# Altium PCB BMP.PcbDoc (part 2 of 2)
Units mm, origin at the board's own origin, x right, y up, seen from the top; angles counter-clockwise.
Board outline 171.87 x 76.56 mm, 2 copper layers (Top Layer, Bottom Layer); 88 components, 25 nets, 514 pads, 181 vias.
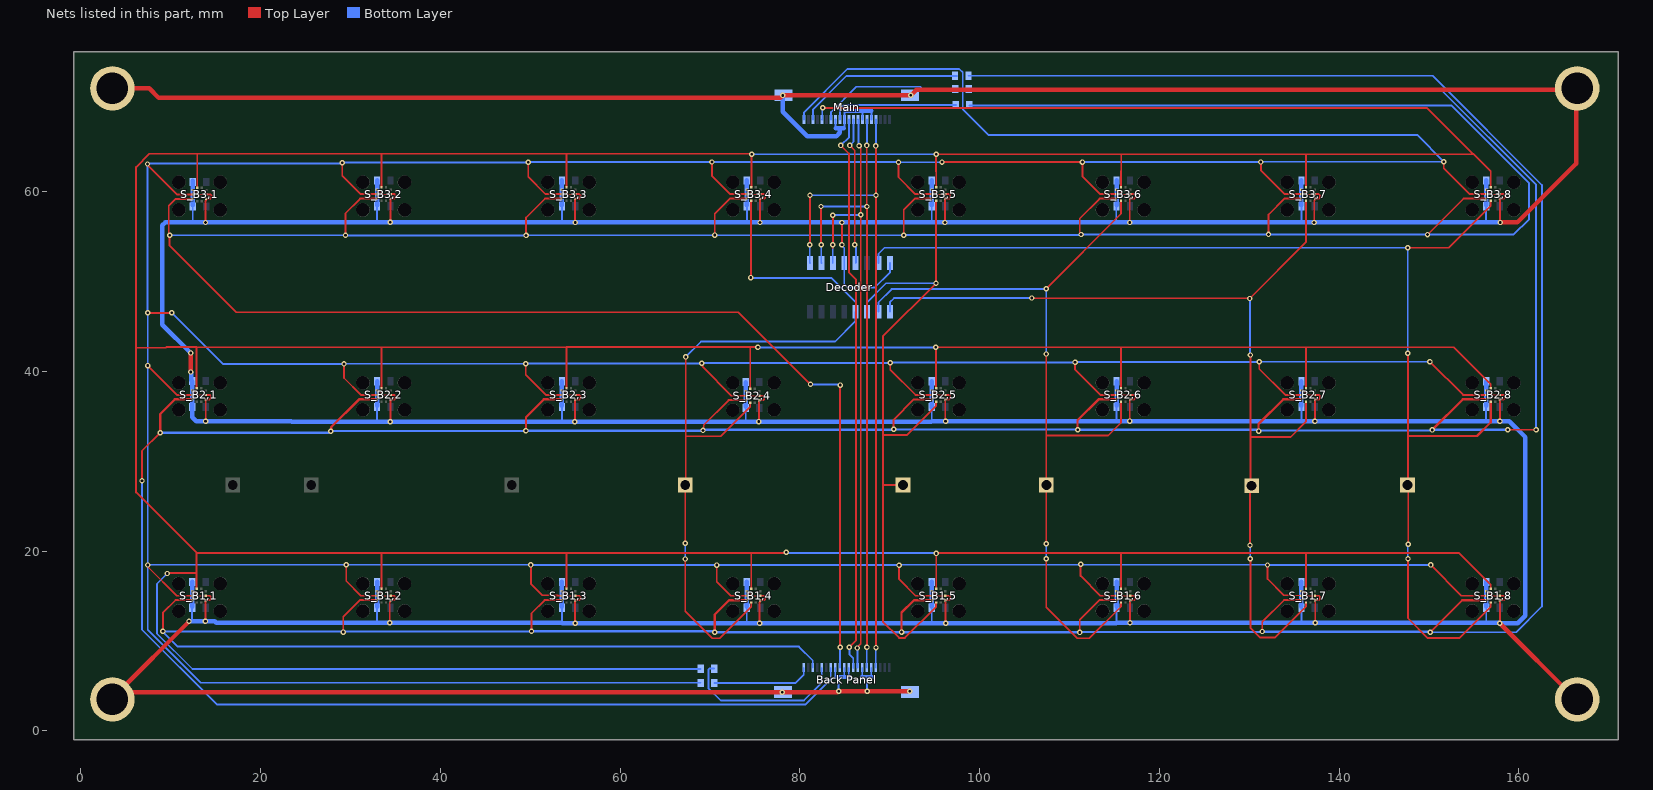
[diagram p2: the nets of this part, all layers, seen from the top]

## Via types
v1: diameter 0.6, hole 0.3, Top Layer to Bottom Layer, tented both sides, 181 vias

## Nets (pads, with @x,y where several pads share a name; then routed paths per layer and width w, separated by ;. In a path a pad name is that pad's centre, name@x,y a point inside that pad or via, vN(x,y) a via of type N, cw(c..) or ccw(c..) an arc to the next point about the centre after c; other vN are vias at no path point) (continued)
CS-4: CS-4.1 Decoder.12 S_B1,4.6 S_B2,4.6 S_B3,4.6 | length 91.5
  Top Layer w0.2: v1(67.246,19.12) 67.246,13.326 70.265,10.307 71.079,10.307 74.591,13.818 74.591,14.283 ; v1(67.246,20.886) CS-4.1@67.246,27.356 67.293,27.402 67.293,32.78 ; v1(67.293,41.613) 67.293,32.78 ; 74.466,36.536 74.466,36.046 71.201,32.78 67.293,32.78 ; v1(74.548,50.443) 74.569,50.464 74.569,58.944 74.589,58.963
  Top Layer w0.254: 74.589,58.963 74.591,58.965
  Bottom Layer w0.2: v1(67.246,19.12) v1(67.246,20.886) ; v1(67.293,41.613) 69.009,43.33 83.935,43.33 86.182,45.578 86.182,46.615 Decoder.12@86.208,46.64 86.208,47.703 83.509,50.402 74.862,50.402
CS-5: CS-5.1 Decoder.11 S_B1,5.6 S_B2,5.6 S_B3,5.6 | length 77.4
  Top Layer w0.2: CS-5.1@91.491,27.356 89.239,27.356 ; 95.164,14.283 95.164,13.818 91.687,10.341 91.046,10.341 89.239,12.149 89.239,27.356 ; 95.164,36.624 95.164,36.187 91.884,32.907 90.161,32.907 89.239,32.907 ; 95.164,58.965 95.156,58.957 95.156,49.817 89.239,43.9 89.239,32.907 ; 89.239,27.356 89.239,32.907
  Bottom Layer w0.2: Decoder.11@87.478,46.64 87.478,47.703 89.584,49.809 v1(95.148,49.809)
CS-6: CS-6.1 Decoder.10 S_B1,6.6 S_B2,6.6 S_B3,6.6 | length 91.9
  Top Layer w0.2: v1(107.399,49.208) 115.735,57.544 115.735,58.927 115.737,58.929 115.737,58.965 ; v1(107.416,19.142) 107.416,13.748 110.862,10.301 112.22,10.301 115.737,13.818 115.737,14.283 ; v1(107.425,20.836) CS-6.1@107.425,27.356 107.425,32.857 ; v1(107.425,41.938) 107.425,32.857 ; 115.737,36.624 115.737,34.304 114.289,32.857 110.634,32.857 107.425,32.857
  Bottom Layer w0.2: Decoder.10@88.748,46.64 88.748,47.703 90.2,49.155 107.347,49.155 v1(107.399,49.208) 107.412,49.195 107.412,41.95 v1(107.425,41.938) ; v1(107.416,19.142) 107.42,19.147 107.42,20.832 v1(107.425,20.836)
CS-7: CS-7.1 Decoder.9 S_B1,7.6 S_B2,7.6 S_B3,7.6 | length 109.2
  Top Layer w0.2: v1(105.799,48.166) 105.824,48.141 130.031,48.141 v1(130.056,48.116) 136.31,54.369 136.31,58.965 ; v1(130.084,20.666) 130.084,27.087 CS-7.1@130.277,27.28 130.135,27.421 130.135,32.704 ; v1(130.132,19.146) 130.132,11.453 131.182,10.403 132.885,10.403 136.31,13.827 136.31,14.283 ; v1(130.135,41.826) 130.135,32.704 ; 136.31,36.624 136.31,34.405 134.609,32.704 130.135,32.704
  Bottom Layer w0.2: Decoder.9@90.018,46.64 90.018,47.703 90.481,48.166 v1(105.799,48.166) ; v1(130.056,48.116) 130.096,48.076 130.096,41.865 v1(130.135,41.826) ; v1(130.084,20.666) 130.108,20.642 130.108,19.17 v1(130.132,19.146)
CS-8: CS-8.1 Decoder.7 S_B1,8.6 S_B2,8.6 S_B3,8.6 | length 137.4
  Top Layer w0.2: CS-8.1@147.627,27.356 147.701,27.281 v1(147.701,20.777) ; v1(147.626,42.016) 147.681,41.962 147.681,32.808 ; v1(147.658,53.754) 152.183,53.754 156.883,58.454 156.883,58.965 ; v1(147.669,19.146) 147.669,12.534 149.877,10.327 153.391,10.327 156.883,13.818 156.883,14.283
  Top Layer w0.254: CS-8.1@147.627,27.356 147.681,27.41 147.681,32.808 155.337,32.808 156.883,34.353 156.883,36.624
  Bottom Layer w0.2: Decoder.7@88.748,52.064 88.748,53.085 89.417,53.754 v1(147.658,53.754) ; v1@147.642,42.032 v1@147.642,53.739 ; v1@147.648,20.536 147.648,19.167 v1(147.669,19.146)
  Bottom Layer w0.254: v1(147.626,42.016) v1@147.642,42.032 ; v1@147.648,20.536 147.648,20.724 v1(147.701,20.777)
DEC_A0: "Back Panel.4" Decoder.1 Main.17 | length 75.9
  Top Layer w0.2: v1(81.102,54.104) 81.115,54.117 81.115,59.576 v1(81.128,59.588) ; v1@88.461,65.067 88.461,59.717 v1@88.514,59.665 ; v1@88.507,9.296 88.468,9.335 88.468,59.575 v1@88.507,59.614
  Bottom Layer w0.2: v1(81.102,54.104) 81.102,52.09 Decoder.1@81.128,52.064 ; v1(81.128,59.588) 81.14,59.601 88.456,59.601 v1(88.468,59.614) ; 88.44,7.031 88.454,7.044 88.454,9.256 v1(88.467,9.269) ; v1(88.454,65.093) 88.46,65.099 88.46,68.015 Main.17@88.466,68.021
DEC_A1: "Back Panel.6" Decoder.2 Main.15 | length 72.5
  Top Layer w0.2: v1(82.353,58.353) 82.364,58.343 82.364,54.106 v1@82.374,54.095 ; v1(87.446,65.148) 87.452,65.142 87.452,58.355 87.46,58.347 v1@87.46,9.182
  Bottom Layer w0.2: v1(82.353,58.353) v1(87.458,58.353) ; v1@82.374,54.095 82.374,52.088 Decoder.2@82.398,52.064 ; 87.44,7.031 87.451,7.041 87.451,9.286 v1(87.461,9.296) ; v1@87.446,65.151 87.456,65.161 87.456,68.011 Main.15@87.466,68.021
  other v1: 82.374,54.104
DEC_A2: "Back Panel.8" Decoder.3 Main.13 | length 69.7
  Top Layer w0.2: 83.668,53.746 83.668,54.102 83.67,54.104 83.67,57.375 v1(83.673,57.378) ; v1(86.385,9.22) 86.385,9.32 86.781,9.715 v1(86.781,57.438) ; v1(86.589,65.126) 86.589,65.017 86.781,64.825 v1@86.781,57.461
  Bottom Layer w0.2: Decoder.3@83.668,52.064 83.668,53.746 ; v1(83.673,57.378) 83.703,57.408 86.751,57.408 v1(86.781,57.438) ; v1(86.385,9.22) 86.413,9.193 86.413,7.059 86.44,7.031 ; Main.13@86.466,68.021 86.516,67.971 86.516,65.198 v1(86.589,65.126)
  other v1: 83.668,54.104
DEC_E3_1: Decoder.5 Main.12 | length 16.4
  Top Layer w0.2: v1(85.544,65.148) 86.106,64.586 v1(86.106,54.104)
  Bottom Layer w0.2: v1(85.544,65.148) 85.544,65.152 85.966,65.574 Main.12@85.966,68.021 ; v1(86.106,54.104) 86.106,53.996 86.233,53.869 86.233,52.09 Decoder.5@86.208,52.064
DEC_E3_2: "Back Panel.9" Main.11 | length 62.6
  Top Layer w0.2: v1@84.557,65.075 84.63,65.075 85.452,64.253 85.452,51.045 86.239,50.258 86.239,10.03 v1(85.506,9.296)
  Bottom Layer w0.2: v1(84.557,65.148) 85.471,66.063 85.471,68.016 Main.11@85.466,68.021 ; v1(85.506,9.296) 85.506,8.527 85.94,8.092 85.94,7.031 85.94,6.985
GND: "Back Panel.5" "Back Panel.7" "Back Panel.10" "Back Panel.11" "Back Panel.13" "Back Panel.MP1" "Back Panel.MP2" C1_B1,1.1 C1_B1,2.1 C1_B1,3.1 C1_B1,4.1 C1_B1,5.1 C1_B1,6.1 C1_B1,7.1 C1_B1,8.1 C1_B2,1.1 C1_B2,2.1 C1_B2,3.1 C1_B2,4.1 C1_B2,5.1 C1_B2,6.1 C1_B2,7.1 C1_B2,8.1 C1_B3,1.1 C1_B3,2.1 C1_B3,3.1 C1_B3,4.1 C1_B3,5.1 C1_B3,6.1 C1_B3,7.1 C1_B3,8.1 C2_B1,1.1 C2_B1,2.1 C2_B1,3.1 C2_B1,4.1 C2_B1,5.1 C2_B1,6.1 C2_B1,7.1 C2_B1,8.1 C2_B2,1.1 C2_B2,2.1 C2_B2,3.1 C2_B2,4.1 C2_B2,5.1 C2_B2,6.1 C2_B2,7.1 C2_B2,8.1 C2_B3,1.1 C2_B3,2.1 C2_B3,3.1 C2_B3,4.1 C2_B3,5.1 C2_B3,6.1 C2_B3,7.1 C2_B3,8.1 Decoder.4 Decoder.8 Main.8 Main.10 Main.14 Main.16 Main.MP1 Main.MP2 pad.1 pad.2@166.5,3.5 pad.3@166.5,71.5 pad.4@3.5,71.5 S_B1,1.3 S_B1,1.8 S_B1,1.9 S_B1,2.3 S_B1,2.8 S_B1,2.9 S_B1,3.3 S_B1,3.8 S_B1,3.9 S_B1,4.3 S_B1,4.8 S_B1,4.9 S_B1,5.3 S_B1,5.8 S_B1,5.9 S_B1,6.3 S_B1,6.8 S_B1,6.9 S_B1,7.3 S_B1,7.8 S_B1,7.9 S_B1,8.3 S_B1,8.8 S_B1,8.9 S_B2,1.3 S_B2,1.8 S_B2,1.9 S_B2,2.3 S_B2,2.8 S_B2,2.9 S_B2,3.3 S_B2,3.8 S_B2,3.9 S_B2,4.3 S_B2,4.8 S_B2,4.9 S_B2,5.3 S_B2,5.8 S_B2,5.9 S_B2,6.3 S_B2,6.8 S_B2,6.9 S_B2,7.3 S_B2,7.8 S_B2,7.9 S_B2,8.3 S_B2,8.8 S_B2,8.9 S_B3,1.3 S_B3,1.8 S_B3,1.9 S_B3,2.3 S_B3,2.8 S_B3,2.9 S_B3,3.3 S_B3,3.8 S_B3,3.9 S_B3,4.3 S_B3,4.8 S_B3,4.9 S_B3,5.3 S_B3,5.8 S_B3,5.9 S_B3,6.3 S_B3,6.8 S_B3,6.9 S_B3,7.3 S_B3,7.8 S_B3,7.9 S_B3,8.3 S_B3,8.8 S_B3,8.9 | length 1067.2
  Top Layer w0.127: 12.359,15.546 12.421,15.485 12.561,15.485 12.999,15.046 13.883,15.046 ; 12.359,37.887 12.421,37.826 12.561,37.826 12.999,37.387 13.883,37.387 ; 12.436,60.2 12.497,60.138 12.637,60.138 13.076,59.7 13.96,59.7 ; 32.932,15.546 32.994,15.485 33.134,15.485 33.572,15.046 34.456,15.046 ; 32.932,37.887 32.994,37.826 33.134,37.826 33.572,37.387 34.456,37.387 ; 32.932,60.228 32.994,60.166 33.134,60.166 33.572,59.728 34.456,59.728 ; 53.505,15.546 53.567,15.485 53.707,15.485 54.145,15.046 55.029,15.046 ; 53.505,37.887 53.567,37.826 53.707,37.826 54.145,37.387 55.029,37.387 ; 53.505,60.228 53.567,60.166 53.707,60.166 54.145,59.728 55.029,59.728 ; 73.954,37.799 74.016,37.737 74.156,37.737 74.594,37.299 75.478,37.299 ; 74.078,15.546 74.14,15.485 74.28,15.485 74.718,15.046 75.602,15.046 ; 74.078,60.228 74.14,60.166 74.28,60.166 74.718,59.728 75.602,59.728 ; 94.651,15.546 94.713,15.485 94.853,15.485 95.291,15.046 96.175,15.046 ; 94.651,37.887 94.713,37.826 94.853,37.826 95.291,37.387 96.175,37.387 ; 94.651,60.228 94.713,60.166 94.853,60.166 95.291,59.728 96.175,59.728 ; 115.224,15.546 115.286,15.485 115.426,15.485 115.864,15.046 116.748,15.046 ; 115.224,37.887 115.286,37.826 115.426,37.826 115.864,37.387 116.748,37.387 ; 115.224,60.228 115.286,60.166 115.426,60.166 115.864,59.728 116.748,59.728 ; 135.797,15.546 135.859,15.485 135.999,15.485 136.437,15.046 137.321,15.046 ; 135.797,37.887 135.859,37.826 135.999,37.826 136.437,37.387 137.321,37.387 ; 135.797,60.228 135.859,60.166 135.999,60.166 136.437,59.728 137.321,59.728 ; 156.37,15.546 156.432,15.485 156.572,15.485 157.01,15.046 157.894,15.046 ; 156.37,37.887 156.432,37.826 156.572,37.826 157.01,37.387 157.894,37.387 ; 156.37,60.228 156.432,60.166 156.572,60.166 157.01,59.728 157.894,59.728
  Top Layer w0.2: v1(13.851,12.2) 13.867,12.216 13.867,14.53 13.883,14.546 14.321,14.546 14.438,14.664 14.438,14.919 14.311,15.046 13.883,15.046 ; v1(13.858,56.574) 13.873,56.588 13.873,58.975 13.922,59.024 13.922,59.175 13.947,59.2 13.96,59.2 14.397,59.2 14.514,59.317 14.514,59.573 14.387,59.7 13.96,59.7 ; v1@13.883,34.628 13.883,36.887 14.321,36.887 14.438,37.004 14.438,37.26 14.311,37.387 13.883,37.387 ; v1@34.369,12.014 34.369,14.321 34.419,14.371 34.419,14.521 34.444,14.546 34.456,14.546 34.894,14.546 35.011,14.664 35.011,14.919 34.884,15.046 34.456,15.046 ; v1(34.424,34.399) 34.44,34.415 34.44,36.871 34.456,36.887 34.894,36.887 35.011,37.004 35.011,37.26 34.884,37.387 34.456,37.387 ; v1(34.427,56.601) 34.442,56.616 34.442,59.213 34.456,59.228 34.894,59.228 35.011,59.345 35.011,59.601 34.884,59.728 34.456,59.728 ; v1(54.992,11.963) 54.992,14.521 55.017,14.546 55.029,14.546 55.467,14.546 55.584,14.664 55.584,14.919 55.457,15.046 55.029,15.046 ; v1@54.992,34.412 54.992,36.862 55.017,36.887 55.029,36.887 55.467,36.887 55.584,37.004 55.584,37.26 55.457,37.387 55.029,37.387 ; v1(54.992,56.574) 54.992,59.203 55.017,59.228 55.029,59.228 55.467,59.228 55.584,59.345 55.584,59.601 55.457,59.728 55.029,59.728 ; v1@75.441,34.628 75.441,36.774 75.466,36.799 75.478,36.799 75.916,36.799 76.033,36.916 76.033,37.172 75.906,37.299 75.478,37.299 ; v1@75.515,11.996 75.515,14.289 75.565,14.339 75.565,14.521 75.59,14.546 75.602,14.546 76.04,14.546 76.157,14.664 76.157,14.919 76.03,15.046 75.602,15.046 ; v1(75.565,56.574) 75.565,59.203 75.59,59.228 75.602,59.228 76.04,59.228 76.157,59.345 76.157,59.601 76.03,59.728 75.602,59.728 ; v1(84.677,54.104) v1(84.677,56.568) ; v1(96.138,56.574) 96.138,59.203 96.163,59.228 96.175,59.228 96.613,59.228 96.73,59.345 96.73,59.601 96.603,59.728 96.175,59.728 ; 96.175,15.046 96.603,15.046 96.73,14.919 96.73,14.664 96.613,14.546 96.175,14.546 96.199,14.523 v1@96.199,11.963 ; v1@96.175,34.627 96.175,36.887 96.613,36.887 96.73,37.004 96.73,37.26 96.603,37.387 96.175,37.387 ; v1@116.711,34.499 116.711,36.862 116.736,36.887 116.748,36.887 117.186,36.887 117.303,37.004 117.303,37.26 117.176,37.387 116.748,37.387 ; v1(116.711,56.574) 116.711,59.203 116.736,59.228 116.748,59.228 117.186,59.228 117.303,59.345 117.303,59.601 117.176,59.728 116.748,59.728 ; v1(116.738,12.014) 116.738,14.536 116.748,14.546 117.186,14.546 117.303,14.664 117.303,14.919 117.176,15.046 116.748,15.046 ; v1@137.234,56.842 137.234,59.003 137.284,59.052 137.284,59.203 137.309,59.228 137.321,59.228 137.759,59.228 137.876,59.345 137.876,59.601 137.749,59.728 137.321,59.728 ; 137.321,15.046 137.749,15.046 137.876,14.919 137.876,14.664 137.759,14.546 137.321,14.546 137.342,14.526 137.342,12.035 v1(137.363,12.014) ; 137.321,36.887 137.317,36.883 137.317,34.632 v1@137.359,34.59 ; 137.321,37.387 137.749,37.387 137.876,37.26 137.876,37.004 137.759,36.887 137.334,36.887 ; v1(157.886,11.989) 157.894,11.997 157.894,14.407 ; 157.894,14.546 158.332,14.546 158.449,14.664 158.449,14.919 158.322,15.046 157.894,15.046 ; 157.894,37.387 158.322,37.387 158.449,37.26 158.449,37.004 158.332,36.887 157.894,36.887 157.898,36.883 157.898,34.454 v1(157.902,34.45) ; 157.894,59.728 158.322,59.728 158.449,59.601 158.449,59.345 158.332,59.228 157.895,59.228 157.92,59.203 v1@157.92,56.599
  Top Layer w0.5: pad.1@3.5,3.5 3.5,3.651 pad.1@4.15,4.3 ; pad.4@3.5,71.5 7.596,71.5 8.661,70.434 77.799,70.434 78.078,70.714 v1(78.105,70.714) ; v1(12.022,12.2) 12.022,12.173 pad.1@4.15,4.3 ; v1(12.218,39.937) v1(12.218,42.053) ; v1@78.151,70.726 v1@92.316,70.726 ; v1(92.236,4.418) 92.165,4.418 92.141,4.394 84.312,4.394 v1(84.309,4.397) 84.282,4.397 84.198,4.313 v1(78.034,4.313) 78.015,4.294 4.156,4.294 pad.1@4.15,4.3 ; v1(92.329,70.739) 92.356,70.739 92.94,71.323 pad.3@166.37,71.323 ; v1(157.886,11.989) 166.375,3.5 pad.2@166.5,3.5 ; v1@157.92,56.599 v1(157.945,56.574) 159.837,56.574 166.395,63.132 166.395,71.395 pad.3@166.5,71.5
  Bottom Layer w0.2: 12.372,12.2 12.372,13.699 ; 12.448,56.574 12.448,58.352 ; 32.945,12.251 32.945,13.699 ; 32.945,34.527 32.945,36.039 ; 32.945,56.65 32.945,58.38 ; 53.518,11.989 53.518,12.014 53.518,13.699 ; 53.518,34.508 53.518,36.039 ; 53.518,56.587 53.518,58.38 ; 73.966,35.951 73.981,35.936 73.981,35.115 73.981,34.628 ; 74.091,12.141 74.091,13.699 ; 74.091,58.38 74.125,58.345 74.125,56.574 ; v1(78.105,70.714) 78.113,70.721 Main.MP1@78.166,70.721 ; 83.94,7.031 83.94,6.084 84.03,5.994 ; 83.966,67.071 Main.8@83.966,68.021 ; v1(84.309,4.397) 84.309,5.994 ; v1(84.677,54.104) 84.677,53.996 84.938,53.736 Decoder.4@84.938,52.064 84.938,50.562 84.931,50.556 84.931,49.716 85.315,49.333 88.349,49.333 90.018,51.002 Decoder.8@90.018,52.064 ; 84.836,5.994 84.94,6.099 84.94,7.031 ; 84.881,67.071 84.966,67.156 Main.10@84.966,68.021 84.966,68.905 85.056,68.995 ; 85.44,7.031 85.44,6.136 85.582,5.994 ; 86.893,5.99 86.94,6.037 86.94,7.031 ; Main.14@86.966,68.021 86.966,69.012 ; 87.475,5.99 87.475,4.427 v1(87.49,4.412) ; 87.94,7.031 87.94,6.106 88.057,5.99 ; Main.16@87.966,68.021 87.966,69.012 ; 94.664,12.014 94.664,13.699 ; 94.664,34.45 94.664,35.939 ; 94.664,56.574 94.664,58.38 ; 115.197,56.574 115.197,58.34 115.237,58.38 ; 115.237,12.014 115.237,13.699 ; 115.237,34.508 115.237,36.039 ; 135.81,12.094 135.81,13.699 ; 135.81,34.468 135.81,36.039 ; 135.81,56.808 135.81,58.38 ; 156.345,34.45 156.345,36.002 156.383,36.039 156.383,36.172 ; 156.345,56.574 156.345,58.342 156.383,58.38 ; 156.383,12.008 156.383,13.699
  Bottom Layer w0.5: v1(12.022,12.2) 12.372,12.2 v1(13.851,12.2) 13.87,12.181 14.873,12.181 15.04,12.014 v1(34.366,12.014) 53.518,12.014 53.568,11.963 v1(54.992,11.963) v1(75.514,11.963) v1(96.241,11.963) ; v1(12.218,39.937) 12.218,39.91 12.278,39.85 12.278,39.021 12.378,38.921 ; v1(12.218,42.053) 9.06,45.21 9.06,56.247 9.387,56.574 12.448,56.574 v1(13.858,56.574) 13.872,56.587 34.413,56.587 v1(34.427,56.601) 34.44,56.587 53.518,56.587 54.978,56.587 v1(54.992,56.574) 74.125,56.574 v1(75.565,56.574) 75.568,56.571 84.674,56.571 v1(84.677,56.568) ; 12.371,13.831 12.371,16.566 ; 12.372,36.039 12.372,34.886 12.815,34.442 v1(13.868,34.442) 23.398,34.442 23.442,34.399 v1(34.424,34.399) 54.947,34.399 v1(54.961,34.412) ; 12.371,36.172 12.375,36.175 12.375,38.904 ; 12.438,58.494 12.438,61.21 ; 32.944,13.831 32.944,16.566 ; 32.944,36.172 32.944,38.907 ; 32.944,58.513 32.944,61.247 ; 53.517,13.831 53.517,16.566 ; 53.517,36.172 53.517,38.907 ; 53.517,58.513 53.517,61.247 ; 73.966,36.084 73.966,38.819 ; 74.09,13.831 74.09,16.566 ; 74.09,58.513 74.09,61.247 ; v1(78.105,70.714) 78.105,68.88 80.805,66.179 84.072,66.179 84.441,66.548 84.441,67.071 ; 83.966,67.071 84.441,67.071 ; 84.03,5.994 84.309,5.994 84.836,5.994 85.582,5.994 ; v1@84.724,56.574 94.664,56.574 v1(96.138,56.574) 115.197,56.574 v1(116.711,56.574) v1(137.22,56.574) 156.345,56.574 v1(157.945,56.574) ; 84.881,67.071 84.441,67.071 ; 85.056,68.995 85.073,69.012 86.966,69.012 87.966,69.012 ; 86.893,5.99 87.475,5.99 88.057,5.99 ; 94.663,13.831 94.663,16.566 ; 94.663,36.172 94.663,38.907 ; 94.663,58.513 94.663,61.247 ; v1@96.287,11.963 115.186,11.963 115.237,12.014 v1(116.738,12.014) v1(137.363,12.014) 137.369,12.008 156.383,12.008 157.84,12.008 v1@157.854,12.021 ; 115.236,13.831 115.236,16.566 ; 115.236,36.172 115.236,38.907 ; 115.236,58.513 115.236,61.247 ; 135.809,13.831 135.809,16.566 ; 135.809,36.172 135.809,38.907 ; 135.809,58.513 135.809,61.247 ; v1(137.312,34.45) 156.345,34.45 v1(157.902,34.45) 158.955,34.45 160.71,32.696 160.71,12.811 159.888,11.989 v1(157.886,11.989) ; 156.382,13.831 156.382,16.566 ; 156.382,36.172 156.382,38.907 ; 156.382,58.513 156.382,61.247
  Bottom Layer w0.508: v1(54.961,34.412) 54.966,34.417 v1(75.413,34.417) 94.63,34.417 94.664,34.45 v1(96.212,34.45) 115.745,34.45 115.751,34.457 116.687,34.457 v1(116.705,34.475) ; 94.664,35.939 94.664,36.039 ; v1@116.736,34.457 117.765,34.457 117.772,34.45 v1(137.312,34.45)
MISO-1: "Back Panel.18" R3.1 S_B1,1.5 S_B1,2.5 S_B1,3.5 S_B1,4.5 S_B1,5.5 S_B1,6.5 S_B1,7.5 S_B1,8.5 | length 396
  Top Layer w0.2: v1(9.119,11.1) 9.119,13.146 10.52,14.546 12.359,14.546 ; v1(29.182,10.995) 29.182,12.712 31.016,14.546 32.932,14.546 ; v1(50.136,11.099) 50.136,13.093 51.589,14.546 53.505,14.546 ; v1(111.133,10.955) 111.133,12.371 113.308,14.546 115.224,14.546 ; v1(131.453,11.057) 131.453,12.127 133.872,14.546 135.797,14.546
  Top Layer w0.254: v1(70.536,10.961) 70.536,12.959 72.124,14.546 74.078,14.546 ; v1(91.317,10.995) 91.317,13.167 92.697,14.546 94.651,14.546 ; v1(150.147,10.981) 153.713,14.546 156.37,14.546
  Bottom Layer w0.2: v1(9.119,11.1) 9.119,11.015 10.755,9.379 79.892,9.379 81.44,7.831 81.44,7.031 ; v1@9.122,11.048 29.13,11.048 v1(29.182,10.995) 29.234,11.047 50.084,11.047 v1(50.136,11.099) ; R3.1@98.769,72.898 150.413,72.898 162.579,60.732 162.579,13.845 159.715,10.981 v1(150.147,10.981)
  Bottom Layer w0.254: v1(50.136,11.099) 70.305,11.099 70.443,10.961 v1(70.536,10.961) 70.554,10.978 91.3,10.978 v1(91.317,10.995) 91.337,10.975 111.113,10.975 v1(111.133,10.955) 111.184,11.006 131.402,11.006 v1(131.453,11.057) 131.491,11.019 150.109,11.019 v1(150.147,10.981)
MOSI-1: Main.1 R4.1 S_B1,1.4 S_B1,2.4 S_B1,3.4 S_B1,4.4 S_B1,5.4 S_B1,6.4 S_B1,7.4 S_B1,8.4 S_B2,1.4 S_B2,2.4 S_B2,3.4 S_B2,4.4 S_B2,5.4 S_B2,6.4 S_B2,7.4 S_B2,8.4 S_B3,1.4 S_B3,2.4 S_B3,3.4 S_B3,4.4 S_B3,5.4 S_B3,6.4 S_B3,7.4 S_B3,8.4 | length 781.9
  Top Layer w0.2: v1(7.399,63.076) 7.476,63 7.476,62.876 10.653,59.7 12.436,59.7 ; v1(7.425,40.648) 7.425,40.612 10.65,37.387 12.359,37.387 ; v1(7.425,46.515) v1(10.092,46.515) ; v1(7.442,18.46) 7.519,18.384 7.519,18.178 10.65,15.046 12.359,15.046 ; v1(29.071,63.209) 29.071,61.778 31.121,59.728 32.932,59.728 ; v1(29.269,40.834) 29.269,39.265 31.147,37.387 32.932,37.387 ; v1(29.515,18.491) 29.515,16.679 31.147,15.046 32.932,15.046 ; v1(49.494,40.86) 49.494,39.613 51.72,37.387 53.505,37.387 ; v1(49.768,63.268) 49.768,61.654 51.694,59.728 53.505,59.728 ; v1(50.063,18.466) 50.063,16.383 51.341,15.105 52.618,15.07 52.624,15.07 52.984,15.07 53.106,15.057 53.505,15.046 ; v1(69.096,40.902) 69.173,40.826 69.173,40.507 72.381,37.299 73.954,37.299 ; v1(70.214,63.305) 70.214,61.781 72.267,59.728 74.078,59.728 ; v1(70.742,18.448) 70.742,16.597 72.293,15.046 74.078,15.046 ; v1(90.051,40.978) 90.051,40.202 92.866,37.387 94.651,37.387 ; v1(90.97,63.271) 90.97,61.598 92.84,59.728 94.651,59.728 ; v1(91.039,18.442) 91.039,16.873 92.866,15.046 94.651,15.046 ; v1(95.818,63.296) 95.819,63.294 111.44,63.294 v1(111.442,63.293) 111.442,61.699 113.413,59.728 115.224,59.728 ; v1(110.625,41.004) 110.625,40.201 113.439,37.387 115.224,37.387 ; v1(111.241,18.535) 111.241,17.244 113.439,15.046 115.224,15.046 ; v1(131.123,41.08) 131.123,40.267 134.003,37.387 135.797,37.387 ; v1(131.301,63.305) 131.301,62.404 133.977,59.728 135.797,59.728 ; v1(132.037,18.457) 132.037,16.908 133.835,15.11 135.797,15.046 ; v1(150.113,41.08) 153.805,37.387 156.37,37.387 ; v1(150.191,18.467) 153.611,15.046 156.37,15.046 ; v1(151.657,63.335) 151.657,62.63 154.559,59.728 156.37,59.728
  Bottom Layer w0.2: v1(7.399,63.076) 7.412,63.064 7.412,46.515 7.425,46.503 v1(7.425,40.648) 7.442,40.631 v1(7.442,18.46) ; v1@7.425,63.076 7.491,63.143 29.004,63.143 29.101,63.239 49.738,63.239 49.786,63.287 70.195,63.287 v1(70.214,63.305) 70.231,63.288 90.953,63.288 v1(90.97,63.271) 90.983,63.283 95.805,63.283 v1(95.818,63.296) ; v1(10.092,46.515) 15.773,40.834 v1(29.269,40.834) ; v1@29.337,40.818 29.366,40.847 49.482,40.847 v1(49.494,40.86) ; v1@49.554,40.842 49.593,40.881 69.075,40.881 69.134,40.94 90.013,40.94 90.064,40.991 110.612,40.991 110.663,41.042 131.085,41.042 v1(131.123,41.08) v1(150.113,41.08) ; R4.1@68.973,5.359 13.312,5.359 7.442,11.229 v1(7.442,18.46) ; Main.1@80.466,68.021 80.466,68.821 85.293,73.648 97.743,73.648 98.119,73.272 98.119,69.162 100.964,66.316 148.686,66.316 151.657,63.345 v1(151.657,63.335) 151.642,63.32 131.316,63.32 131.295,63.299 111.448,63.299 v1(111.442,63.293) ; v1@132.037,18.442 132.057,18.462 150.186,18.462 v1(150.191,18.467) ; v1(132.037,18.457) 132.003,18.492 111.284,18.492 v1(111.241,18.535) 111.195,18.488 91.085,18.488 v1(91.039,18.442) 91.036,18.445 70.745,18.445 70.733,18.457 50.072,18.457 50.051,18.479 29.527,18.479 v1(29.515,18.491) 29.499,18.476 7.458,18.476 v1(7.442,18.46)
MOSI-2: "Back Panel.14" R2.1 S_B2,1.5 S_B2,2.5 S_B2,3.5 S_B2,4.5 S_B2,5.5 S_B2,6.5 S_B2,7.5 S_B2,8.5 | length 406
  Top Layer w0.2: v1(6.788,27.846) 6.788,31.153 v1(8.818,33.182) ; v1@69.26,33.471 69.298,33.51 69.298,34.034 72.067,36.803 72.991,36.803 72.995,36.799 73.954,36.799 ; v1(90.432,33.561) 90.432,34.629 92.69,36.887 94.651,36.887 ; v1(158.758,33.511) v1(161.925,33.511)
  Top Layer w0.254: v1(8.818,33.182) 8.818,35.268 10.436,36.887 12.359,36.887 ; v1(27.796,33.333) 27.862,33.399 27.862,33.816 30.933,36.887 32.932,36.887 ; v1(49.513,33.384) 49.513,34.894 51.506,36.887 53.505,36.887 ; v1(69.223,33.434) v1@69.26,33.471 ; v1(110.904,33.511) 110.904,34.566 113.225,36.887 115.214,36.887 ; v1(131.047,33.358) 131.047,34.145 133.789,36.887 135.797,36.887 ; v1(150.354,33.489) 153.753,36.887 156.37,36.887
  Bottom Layer w0.2: v1(6.788,27.846) 6.788,11.261 15.108,2.941 80.632,2.941 83.44,5.75 83.44,7.031 ; R2.1@98.794,71.425 151.264,71.425 161.925,60.764 v1(161.925,33.511)
  Bottom Layer w0.254: v1(8.818,33.182) 27.551,33.182 27.702,33.333 v1(27.796,33.333) 27.821,33.358 49.487,33.358 49.538,33.409 69.198,33.409 69.287,33.498 90.369,33.498 v1(90.432,33.561) 90.457,33.536 110.879,33.536 v1(110.904,33.511) 130.801,33.511 130.953,33.358 v1(131.047,33.358) 131.112,33.423 150.289,33.423 v1(150.354,33.489) ; v1@150.365,33.5 v1@158.741,33.5
MOSI-3: "Back Panel.12" R1.1 S_B3,1.5 S_B3,2.5 S_B3,3.5 S_B3,4.5 S_B3,5.5 S_B3,6.5 S_B3,7.5 S_B3,8.5 | length 389.7
  Top Layer w0.2: 12.436,59.2 10.537,59.2 9.77,58.433 9.77,55.356 9.864,55.262 9.864,54.006 17.289,46.582 73.119,46.582 v1@81.144,38.557 ; v1(29.439,55.143) 29.439,57.605 31.062,59.228 32.932,59.228 ; v1(49.532,55.132) 49.532,57.125 51.635,59.228 53.505,59.228 ; v1(70.532,55.17) 70.532,57.552 72.208,59.228 74.078,59.228 ; v1(84.48,38.481) 84.48,9.322 v1(84.506,9.296) ; v1(91.55,55.145) 91.55,57.997 92.781,59.228 94.651,59.228 ; v1@111.14,55.45 111.14,57.014 113.354,59.228 115.224,59.228 ; v1(132.153,55.243) 132.153,57.463 133.918,59.228 135.797,59.228 ; v1(149.843,55.228) 153.843,59.228 156.37,59.228
  Top Layer w0.254: v1@81.144,38.557 v1(81.178,38.557)
  Bottom Layer w0.2: v1(9.864,55.154) 9.869,55.149 29.433,55.149 29.444,55.138 49.526,55.138 v1(49.532,55.132) 49.551,55.151 70.513,55.151 v1(70.532,55.17) ; v1@70.562,55.2 70.605,55.157 91.538,55.157 v1(91.55,55.145) ; v1(81.178,38.557) 84.404,38.557 v1(84.48,38.481) ; 84.44,7.031 84.473,7.064 84.473,9.264 v1(84.506,9.296) ; v1@91.596,55.185 91.599,55.188 111.248,55.188 v1(111.291,55.231) ; R1.1@98.858,69.596 152.47,69.596 161.147,60.92 161.147,56.917 159.387,55.228 v1(149.843,55.228) 149.835,55.236 132.16,55.236 v1@132.159,55.237 ; v1@111.298,55.237 132.146,55.237 v1(132.153,55.243)
"NetBack Panel_16": "Back Panel.16" R5.2 | length 18.4
  Bottom Layer w0.2: R5.2@70.473,6.909 70.448,6.934 69.94,6.934 69.823,6.817 69.823,4.76 71.202,3.381 80.449,3.381 82.44,5.372 82.44,7.031
"NetBack Panel_20": "Back Panel.20" R4.2 | length 11.1
  Bottom Layer w0.2: R4.2@70.473,5.334 79.543,5.334 80.44,6.231 80.44,7.031
NetMain_3: Main.3 R3.2 | length 18.7
  Bottom Layer w0.2: Main.3@81.466,68.021 81.466,69.182 85.157,72.873 R3.2@97.49,72.873
NetMain_7: Main.7 R2.2 | length 15.9
  Bottom Layer w0.2: Main.7@83.466,68.021 83.466,68.862 86.276,71.671 93.391,71.671 93.637,71.425 R2.2@97.294,71.425
NetMain_9: Main.9 R1.2 | length 14.3
  Bottom Layer w0.2: Main.9@84.466,68.021 84.466,69.24 84.873,69.647 R1.2@97.358,69.647
SCK-1: Main.5 R5.1 S_B1,1.2 S_B1,2.2 S_B1,3.2 S_B1,4.2 S_B1,5.2 S_B1,6.2 S_B1,7.2 S_B1,8.2 S_B2,1.2 S_B2,2.2 S_B2,3.2 S_B2,4.2 S_B2,5.2 S_B2,6.2 S_B2,7.2 S_B2,8.2 S_B3,1.2 S_B3,2.2 S_B3,3.2 S_B3,4.2 S_B3,5.2 S_B3,6.2 S_B3,7.2 S_B3,8.2 | length 732.7
  Top Layer w0.2: v1(9.609,17.509) 9.651,17.551 12.872,17.551 ; 12.872,15.809 12.872,17.551 ; 12.872,38.15 12.872,42.699 ; 12.948,60.463 12.948,62.36 12.948,64.219 ; 33.445,15.809 33.445,19.683 ; 33.445,38.15 33.445,42.699 ; 33.445,60.491 33.434,60.501 33.434,64.219 ; 54.018,15.809 54.018,19.8 ; 54.018,38.15 54.018,40.435 54.034,40.452 54.034,42.699 ; 54.018,60.491 54.018,64.219 ; 74.466,38.062 74.466,40.402 74.466,42.705 ; 74.591,15.809 74.591,19.8 ; 74.591,60.491 74.616,60.516 74.616,64.127 v1(74.649,64.161) 74.591,64.219 54.018,64.219 ; v1(75.332,42.676) 75.303,42.705 74.466,42.705 ; v1(78.474,19.868) 78.405,19.8 74.591,19.8 ; v1(82.532,69.323) 149.756,69.323 154.875,64.204 154.954,64.204 156.883,62.276 156.883,60.491 ; v1@95.149,42.677 95.149,38.165 95.164,38.15 ; 95.164,15.809 95.175,15.821 95.175,19.734 95.241,19.8 115.737,19.8 ; 95.164,60.491 95.164,60.525 95.167,60.528 95.167,62.252 95.164,62.256 95.164,64.158 v1(95.17,64.164) 115.756,64.164 ; v1@95.171,42.699 115.737,42.699 ; 115.737,15.809 115.737,19.8 ; 115.737,38.15 115.737,42.699 ; 115.737,60.491 115.737,62.337 115.756,62.356 115.756,64.164 ; 136.31,15.809 136.31,19.683 136.427,19.8 ; 136.31,38.15 136.31,42.699 ; 136.31,60.491 136.31,62.341 136.319,62.351 136.319,64.164 ; 154.915,64.164 136.319,64.164 ; 156.883,15.809 156.883,16.247 153.33,19.8 136.427,19.8 ; 156.883,38.15 156.883,38.588 152.771,42.699 136.31,42.699 ; 6.134,42.64 6.134,62.736 7.618,64.219 12.948,64.219 ; 6.134,42.64 6.134,26.537 12.872,19.8 ; 6.134,42.64 9.465,42.64 9.532,42.707 12.864,42.707 12.872,42.699 ; 12.872,17.551 12.872,19.8 ; 12.872,19.8 54.018,19.8 ; 12.872,42.699 33.445,42.699 ; 12.948,64.219 33.434,64.219 ; 33.434,64.219 54.018,64.219 ; 33.445,42.699 54.034,42.699 ; 54.018,19.8 74.591,19.8 ; 54.034,42.699 54.04,42.705 74.466,42.705 ; 115.737,19.8 136.427,19.8 ; 115.737,42.699 136.31,42.699 ; 115.756,64.164 136.319,64.164
  Bottom Layer w0.2: v1(9.609,17.509) 8.465,16.364 8.465,10.829 12.41,6.883 R5.1@68.973,6.883 ; v1(74.649,64.161) 74.651,64.163 v1(95.17,64.164) v1(95.17,64.164) ; v1(75.332,42.676) 95.125,42.676 v1(95.134,42.685) ; v1(78.474,19.868) 78.535,19.807 95.126,19.807 v1(95.187,19.746) ; Main.5@82.466,68.021 82.499,68.054 82.499,69.29 v1(82.532,69.323)
pads on no net: S_B1,1.7 S_B1,2.7 S_B1,3.7 S_B1,4.7 S_B1,5.7 S_B1,6.7 S_B1,7.7 S_B1,8.7 S_B2,1.7 S_B2,2.7 S_B2,3.7 S_B2,4.7 S_B2,5.7 S_B2,6.7 S_B2,7.7 S_B2,8.7 S_B3,1.7 S_B3,2.7 S_B3,3.7 S_B3,4.7 S_B3,5.7 S_B3,6.7 S_B3,7.7 S_B3,8.7

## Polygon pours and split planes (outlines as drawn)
GND on Bottom Layer "GND_L02_P001" (solid, remove dead copper, pour order 1): 0.33,74.498 0.33,0.457 0.381,0.406 169.875,0.406 170,0.282 170,75
GND on Top Layer "GND_L01_P000" (solid, remove dead copper, pour order 0): -0.051,75 0,74.949 0,0 170,0 170,75

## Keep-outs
Keep-Out Layer:
  lines w0.254: -0.051,75 0,0 170,0 170,75 0,75 ; 168.504,0.025 168.554,-0.025

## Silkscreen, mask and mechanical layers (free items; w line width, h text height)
Mechanical 6:
  lines w0.254: -0.043,0 0,75 170,75 170,0 0,0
